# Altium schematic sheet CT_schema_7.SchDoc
size 277 x 170 mm
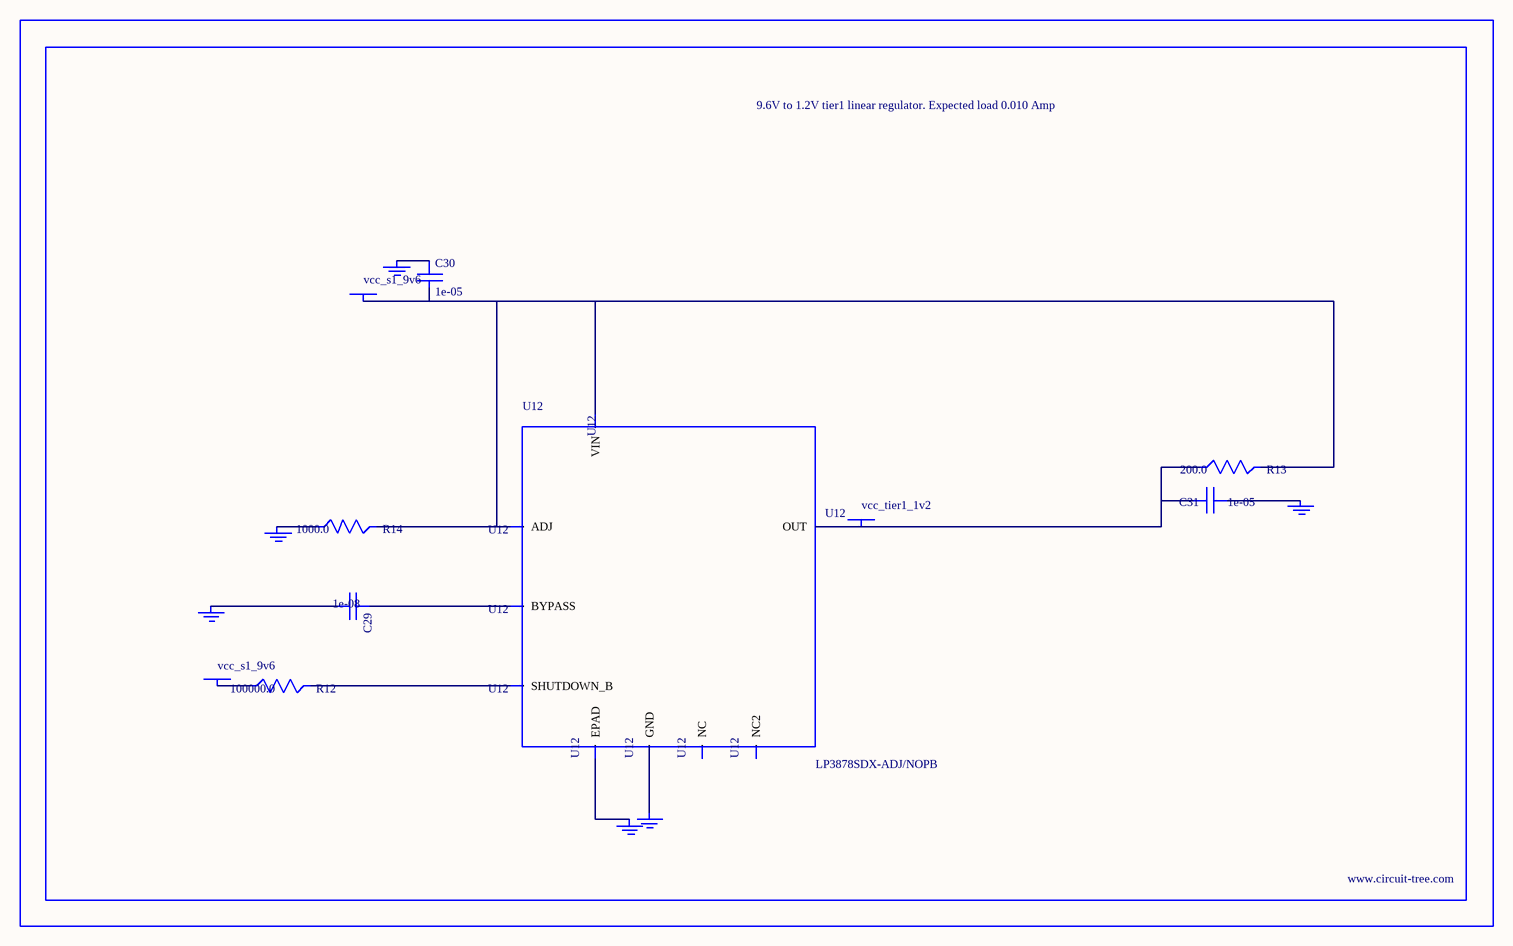
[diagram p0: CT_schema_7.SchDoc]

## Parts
BORDER6  (no value)
C29  1e-08  [C0402]
C30  1e-05  [C1206]
C31  1e-05  [C0805]
GND_INSTANCE_6_0  (no value)
GND_INSTANCE_6_1  (no value)
GND_INSTANCE_6_2  (no value)
GND_INSTANCE_6_3  (no value)
GND_INSTANCE_6_4  (no value)
GND_INSTANCE_6_5  (no value)
POWER_INSTANCE_6_0  vcc_s1_9v6
POWER_INSTANCE_6_1  vcc_s1_9v6
POWER_INSTANCE_6_2  vcc_tier1_1v2
R12  100000.0  [R0603]
R13  200.0  [R0603]
R14  1000.0  [R0603]
U12  LP3878SDX-ADJ/NOPB  [WSON-8]

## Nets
NetC29_1: C29.1 U12.1(BYPASS)
NetC29_2: C29.2 GND_INSTANCE_6_0.0(GND)
NetC30_1: C30.1 GND_INSTANCE_6_1.0(GND)
NetC30_2: C30.2 POWER_INSTANCE_6_0.0(PWR) R13.2 R14.2 U12.4(VIN) U12.6(ADJ)
NetC31_1: C31.1 GND_INSTANCE_6_2.0(GND)
NetC31_2: C31.2 POWER_INSTANCE_6_2.0(PWR) R13.1 U12.5(OUT)
NetGND_INSTANCE_6_3_0: GND_INSTANCE_6_3.0(GND) R14.1
NetGND_INSTANCE_6_4_0: GND_INSTANCE_6_4.0(GND) U12.PAD(EPAD)
NetGND_INSTANCE_6_5_0: GND_INSTANCE_6_5.0(GND) U12.3(GND)
NetPOWER_INSTANCE_6_1_0: POWER_INSTANCE_6_1.0(PWR) R12.1
NetR12_2: R12.2 U12.8(SHUTDOWN_B)

Not connected (* = marked no-connect by the designer): U12 2(NC) 7(NC2)

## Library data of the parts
BORDER6 = BORDER_PAGE6
C29 = C0402C103K3RAC
C30 = C1206C106K3RACTU
C31 = GRM219R60J106ME19D
GND_INSTANCE_6_0-GND_INSTANCE_6_5 = GND
POWER_INSTANCE_6_0-POWER_INSTANCE_6_2 = PWR
R12 = RC0603JR-07100KL
R13 = RC0603JR-07200RL
R14 = RC0603JR-071KL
